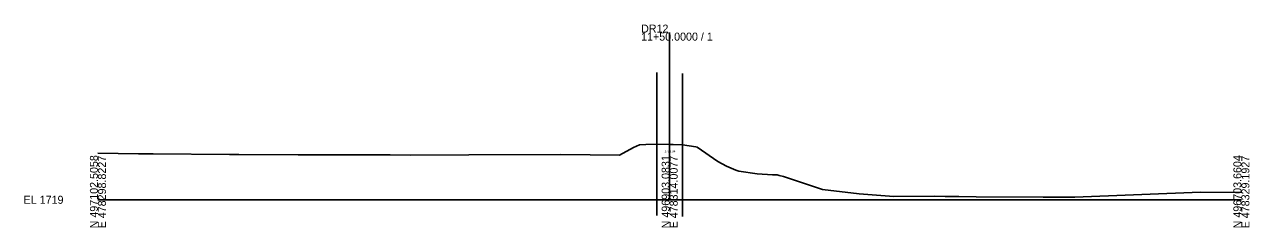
# Model space of a CAD drawing. Extents: x -26 to 403, y -10 to 3574.
# Drawn here: x -25.7 to 402.8, y 2990.3 to 3061.3 of the extents above; entities that cross this region are included whole.
import ezdxf

# ---------------------------------------------------------------- set-up
doc = ezdxf.new("R2010")
doc.units = 0
for name, color, linetype in [('Exist Cross Section Cell', 7, 'Continuous'), ('Exist XS Center Line Elevation Label', 7, 'Continuous'), ('Exist XS Ground Line', 7, 'Continuous'), ('Scratch_Level_1', 7, 'Continuous'), ('Scratch_Level_5', 7, 'Continuous')]:
    doc.layers.add(name, color=color, linetype=linetype)

msp = doc.modelspace()

# ---------------------------------------------------------------- linework, layer by layer
at = {"layer": 'Exist Cross Section Cell'}
for p, q in [((200, 3000), (200, 3058.46)), ((0, 3000), (200, 3000)), ((200, 3000), (400, 3000))]:
    msp.add_line(p, q, dxfattribs=at)
at = {"layer": 'Exist XS Ground Line'}
msp.add_lwpolyline([(0, 3016.26), (14.18, 3016.12), (19.28, 3016.06), (46, 3015.8), (46.51, 3015.8), (49.27, 3015.8), (70.03, 3015.74), (75.45, 3015.75), (97.34, 3015.7), (102.19, 3015.71), (109.18, 3015.61), (129.76, 3015.72), (161.88, 3015.78), (182.43, 3015.65), (187.37, 3018.23), (189.41, 3019.25), (191.68, 3019.37), (195.52, 3019.49), (200, 3019.34), (201.18, 3019.3), (204.49, 3019.2), (209.16, 3018.49), (209.6, 3018.43), (216.87, 3013.42), (219.88, 3011.74), (223.18, 3010.38), (224.25, 3009.96), (230.59, 3009.02), (236.02, 3008.77), (237.58, 3008.7), (238.35, 3008.52), (239.79, 3008.09), (253.47, 3003.63), (266.31, 3002.1), (278.42, 3001.09), (292.67, 3001.23), (296.4, 3001.13), (301.18, 3001.1), (307.22, 3001.08), (330.65, 3000.97), (341.69, 3000.93), (385.68, 3002.64), (400, 3002.55)], dxfattribs=at)
at = {"layer": 'Scratch_Level_1'}
for p, q in [((195.52, 3044.49), (195.52, 2994.49)), ((204.49, 3044.2), (204.49, 2994.2))]:
    msp.add_line(p, q, dxfattribs=at)
at = {"layer": 'Scratch_Level_5'}
msp.add_lwpolyline([(0, 3016.26), (14.18, 3016.12), (19.28, 3016.06), (46, 3015.8), (46.51, 3015.8), (49.27, 3015.8), (70.03, 3015.74), (75.45, 3015.75), (97.34, 3015.7), (102.19, 3015.71), (109.18, 3015.61), (129.76, 3015.72), (161.88, 3015.78), (182.43, 3015.65), (187.37, 3018.23), (189.41, 3019.25), (191.68, 3019.37), (195.52, 3019.49), (200, 3019.34), (201.18, 3019.3), (204.49, 3019.2), (209.16, 3018.49), (209.6, 3018.43), (216.87, 3013.42), (219.88, 3011.74), (223.18, 3010.38), (224.25, 3009.96), (230.59, 3009.02), (236.02, 3008.77), (237.58, 3008.7), (238.35, 3008.52), (239.79, 3008.09), (253.47, 3003.63), (266.31, 3002.1), (278.42, 3001.09), (292.67, 3001.23), (296.4, 3001.13), (301.18, 3001.1), (307.22, 3001.08), (330.65, 3000.97), (341.69, 3000.93), (385.68, 3002.64), (400, 3002.55)], dxfattribs=at)
msp.add_lwpolyline([(0, 3016.26), (14.18, 3016.12), (19.28, 3016.06), (46, 3015.8), (46.51, 3015.8), (49.27, 3015.8), (70.03, 3015.74), (75.45, 3015.75), (97.34, 3015.7), (102.19, 3015.71), (109.18, 3015.61), (129.76, 3015.72), (161.88, 3015.78), (182.43, 3015.65), (187.37, 3018.23), (189.41, 3019.25), (191.68, 3019.37), (195.52, 3019.49), (200, 3019.34), (201.18, 3019.3), (204.49, 3019.2), (209.16, 3018.49), (209.6, 3018.43), (216.87, 3013.42), (219.88, 3011.74), (223.18, 3010.38), (224.25, 3009.96), (230.59, 3009.02), (236.02, 3008.77), (237.58, 3008.7), (238.35, 3008.52), (239.79, 3008.09), (253.47, 3003.63), (266.31, 3002.1), (278.42, 3001.09), (292.67, 3001.23), (296.4, 3001.13), (301.18, 3001.1), (307.22, 3001.08), (330.65, 3000.97), (341.69, 3000.93), (385.68, 3002.64), (400, 3002.55)], dxfattribs=at)

# ---------------------------------------------------------------- texts
at = {"layer": 'Exist Cross Section Cell'}
for s, p in [('DR12', (190, 3058.46)), ('11+50.0000 / 1', (190, 3055.66)), ('EL 1719', (-26, 2998.6))]:
    msp.add_text(s, height=2.8, dxfattribs=at).set_placement(p)
for s, p in [('N 497102.5058', (0, 2990)), ('E 478298.8227', (2.8, 2990)), ('N 496903.0831', (200, 2990)), ('E 478314.0077', (202.8, 2990)), ('N 496703.6604', (400, 2990)), ('E 478329.1927', (402.8, 2990))]:
    msp.add_text(s, height=2.8, rotation=90, dxfattribs=at).set_placement(p)
at = {"layer": 'Exist XS Center Line Elevation Label'}
msp.add_text('1738.34', height=0.75, dxfattribs=at).set_placement((198.22, 3016.59))

doc.saveas('drawing.dxf')
